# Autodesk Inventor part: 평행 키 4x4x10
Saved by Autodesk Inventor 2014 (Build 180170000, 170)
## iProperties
Created: 2026-09
Part Number: 평행 키 4x4x10
Material: 일반
Document SubType Name: Modeling
Designer: dg
Density: 1 g/cm^3
Appearance: 기본값
Author: dg
Author: jhkim
Description: 키 및 해당 키홈
Creation Date: 2026-08-27
Sending System: Autodesk Inventor 2027
Preprocessor: ST-DEVELOPER v20.1
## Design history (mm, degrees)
node "평행 키 4x4x101"
body "Solid1"
node "기준1"
